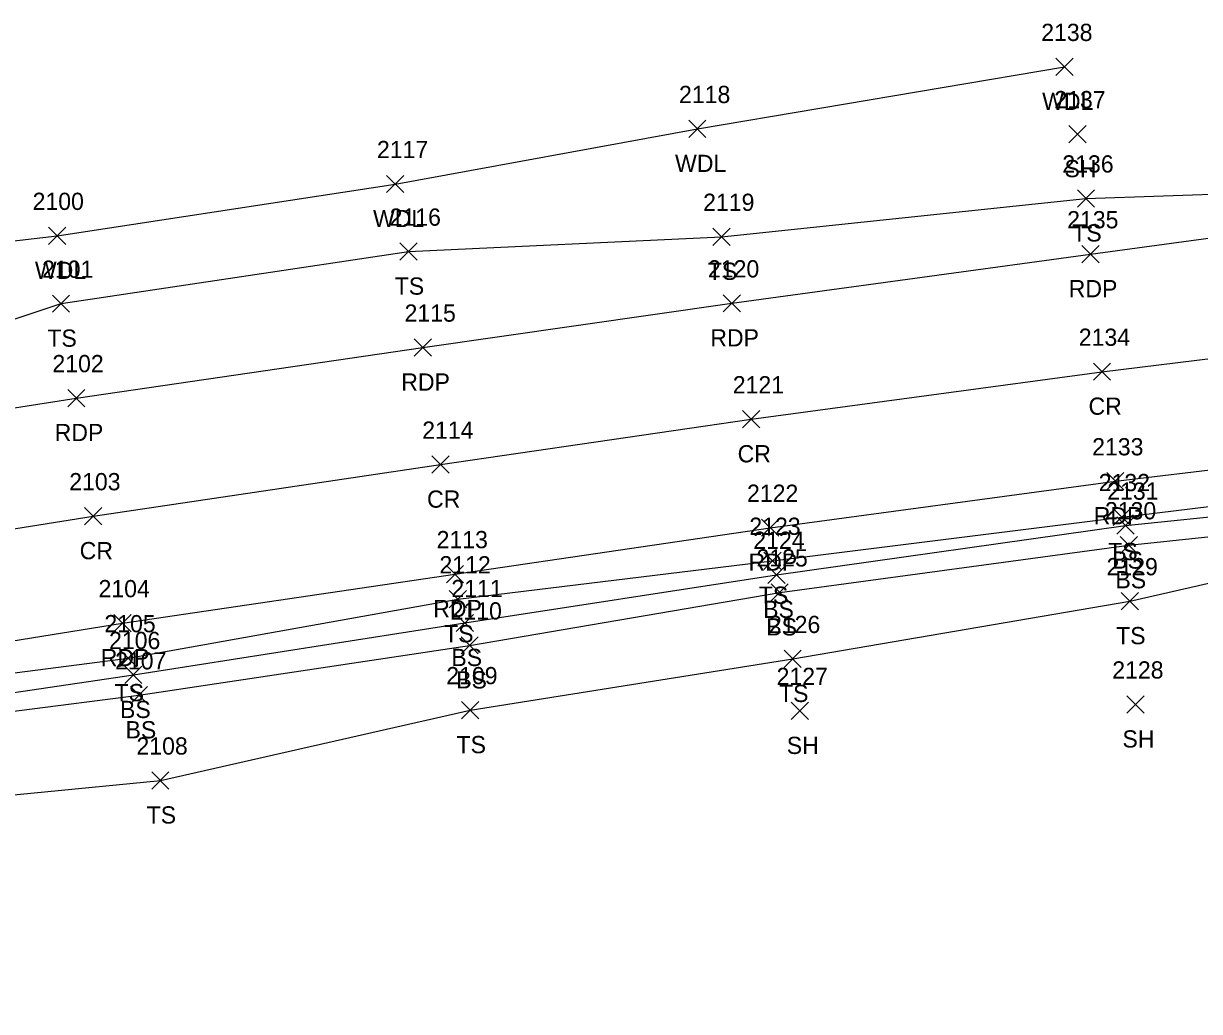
# Model space of a CAD drawing. Extents: x 1611797 to 1633212, y 298978 to 305475.
# Drawn here: x 1614515.3 to 1614651.7, y 301422 to 301536.6 of the extents above; entities that cross this region are included whole.
import ezdxf

# ---------------------------------------------------------------- set-up
doc = ezdxf.new("R2010")
doc.units = 0
for name, color, linetype in [('L_A', 7, 'Continuous'), ('L_I', 7, 'Continuous'), ('L_TIC', 7, 'Continuous'), ('LAWA', 7, 'Continuous'), ('LELB', 7, 'Continuous'), ('P_A', 7, 'Continuous'), ('P_I', 7, 'Continuous'), ('P_TIC', 7, 'Continuous'), ('PET', 7, 'Continuous'), ('PRC', 7, 'Continuous')]:
    doc.layers.add(name, color=color, linetype=linetype)

msp = doc.modelspace()

# ---------------------------------------------------------------- linework, layer by layer
at = {"layer": 'L_TIC'}
for points in [[(1614635.08, 301530.61), (1614637.08, 301532.61)], [(1614637.08, 301530.61), (1614635.08, 301532.61)], [(1614592.49, 301523.41), (1614594.49, 301525.41)], [(1614594.49, 301523.41), (1614592.49, 301525.41)], [(1614636.59, 301522.81), (1614638.59, 301524.81)], [(1614638.59, 301522.81), (1614636.59, 301524.81)], [(1614557.44, 301517.02), (1614559.44, 301519.02)], [(1614559.44, 301517.02), (1614557.44, 301519.02)], [(1614637.57, 301515.35), (1614639.57, 301517.35)], [(1614639.57, 301515.35), (1614637.57, 301517.35)], [(1614518.22, 301511.01), (1614520.22, 301513.01)], [(1614520.22, 301511.01), (1614518.22, 301513.01)], [(1614595.29, 301510.9), (1614597.29, 301512.9)], [(1614597.29, 301510.9), (1614595.29, 301512.9)], [(1614558.97, 301509.18), (1614560.97, 301511.18)], [(1614560.97, 301509.18), (1614558.97, 301511.18)], [(1614518.67, 301503.14), (1614520.67, 301505.14)], [(1614520.67, 301503.14), (1614518.67, 301505.14)], [(1614641.74, 301478.39), (1614643.74, 301480.39)], [(1614643.74, 301478.39), (1614641.74, 301480.39)], [(1614642.17, 301477.4), (1614644.17, 301479.4)], [(1614644.17, 301477.4), (1614642.17, 301479.4)], [(1614642.55, 301475.12), (1614644.55, 301477.12)], [(1614644.55, 301475.12), (1614642.55, 301477.12)], [(1614601.21, 301473.32), (1614603.21, 301475.32)], [(1614603.21, 301473.32), (1614601.21, 301475.32)], [(1614601.68, 301471.69), (1614603.68, 301473.69)], [(1614603.68, 301471.69), (1614601.68, 301473.69)], [(1614564.7, 301468.85), (1614566.7, 301470.85)], [(1614566.7, 301468.85), (1614564.7, 301470.85)], [(1614602.04, 301469.65), (1614604.04, 301471.65)], [(1614604.04, 301469.65), (1614602.04, 301471.65)], [(1614642.66, 301468.63), (1614644.66, 301470.63)], [(1614644.66, 301468.63), (1614642.66, 301470.63)], [(1614565.51, 301466.1), (1614567.51, 301468.1)], [(1614567.51, 301466.1), (1614565.51, 301468.1)], [(1614566.07, 301463.5), (1614568.07, 301465.5)], [(1614568.07, 301463.5), (1614566.07, 301465.5)], [(1614526.47, 301462.02), (1614528.47, 301464.02)], [(1614528.47, 301462.02), (1614526.47, 301464.02)], [(1614603.55, 301461.93), (1614605.55, 301463.93)], [(1614605.55, 301461.93), (1614603.55, 301463.93)], [(1614527.06, 301460.07), (1614529.06, 301462.07)], [(1614529.06, 301460.07), (1614527.06, 301462.07)], [(1614527.71, 301457.71), (1614529.71, 301459.71)], [(1614529.71, 301457.71), (1614527.71, 301459.71)], [(1614643.31, 301456.65), (1614645.31, 301458.65)], [(1614645.31, 301456.65), (1614643.31, 301458.65)], [(1614566.14, 301455.99), (1614568.14, 301457.99)], [(1614568.14, 301455.99), (1614566.14, 301457.99)], [(1614604.37, 301455.9), (1614606.37, 301457.9)], [(1614606.37, 301455.9), (1614604.37, 301457.9)], [(1614530.19, 301447.83), (1614532.19, 301449.83)], [(1614532.19, 301447.83), (1614530.19, 301449.83)]]:
    msp.add_lwpolyline(points, dxfattribs=at)
at = {"layer": 'LAWA'}
msp.add_lwpolyline([(1614366.06, 301492.98), (1614391.26, 301497.25), (1614409.98, 301497.41), (1614429.08, 301502.06), (1614460.11, 301504.85), (1614477.42, 301507.37), (1614492.86, 301508.96), (1614519.22, 301512.01), (1614558.44, 301518.02), (1614593.49, 301524.41), (1614636.08, 301531.61)], dxfattribs=at)
at = {"layer": 'LELB'}
for points in [[(1614431.54, 301482.84), (1614462.05, 301487.3), (1614494.87, 301495.91), (1614519.67, 301504.14), (1614559.97, 301510.18), (1614596.29, 301511.9), (1614638.57, 301516.35), (1614665.6, 301517.26), (1614689.07, 301522.87)], [(1614397.99, 301442.92), (1614427.41, 301447.99), (1614467.33, 301454.21), (1614500.14, 301459.48), (1614527.47, 301463.02), (1614565.7, 301469.85), (1614602.21, 301474.32), (1614642.74, 301479.39), (1614671.43, 301482.88), (1614707.96, 301487.6), (1614751.26, 301491.29), (1614776.62, 301492.25), (1614790.7, 301492.68), (1614828.78, 301494.15), (1614870.95, 301494.61), (1614916.31, 301494.84), (1614940.92, 301495.39), (1614991.32, 301496.48), (1615024.25, 301496.97), (1615079.65, 301497.8)], [(1614388.68, 301423.66), (1614397.1, 301437.78), (1614427.86, 301446.85), (1614467.6, 301452.72), (1614486.89, 301454.32), (1614500.85, 301457.06), (1614528.06, 301461.07), (1614566.51, 301467.1), (1614602.68, 301472.69), (1614643.17, 301478.4), (1614671.68, 301481.35), (1614708.28, 301486.02), (1614751.11, 301488.75), (1614768.89, 301489.17), (1614769.01, 301487.67)], [(1614397.1, 301437.78), (1614428.41, 301444.54), (1614468.12, 301450.7), (1614487.22, 301452.99), (1614500.88, 301455.16), (1614528.71, 301458.71), (1614567.07, 301464.5), (1614603.04, 301470.65), (1614643.55, 301476.12), (1614672.08, 301479.14), (1614708.59, 301484.35), (1614751.86, 301486.59), (1614769.01, 301487.67)], [(1614398.42, 301422.03), (1614407.58, 301431.9), (1614428.91, 301436.83), (1614470.35, 301441.15), (1614511.39, 301446.9), (1614531.19, 301448.83), (1614567.14, 301456.99), (1614604.55, 301462.93), (1614643.66, 301469.63), (1614672.14, 301476.12), (1614708.74, 301481.62), (1614752.08, 301482.44), (1614770.32, 301485.06)]]:
    msp.add_lwpolyline(points, dxfattribs=at)
at = {"layer": 'P_TIC'}
for points in [[(1614638.09, 301508.88), (1614640.09, 301510.88)], [(1614640.09, 301508.88), (1614638.09, 301510.88)], [(1614596.5, 301503.18), (1614598.5, 301505.18)], [(1614598.5, 301503.18), (1614596.5, 301505.18)], [(1614560.65, 301498.05), (1614562.65, 301500.05)], [(1614562.65, 301498.05), (1614560.65, 301500.05)], [(1614639.43, 301495.25), (1614641.43, 301497.25)], [(1614641.43, 301495.25), (1614639.43, 301497.25)], [(1614520.44, 301492.19), (1614522.44, 301494.19)], [(1614522.44, 301492.19), (1614520.44, 301494.19)], [(1614598.72, 301489.73), (1614600.72, 301491.73)], [(1614600.72, 301489.73), (1614598.72, 301491.73)], [(1614562.69, 301484.47), (1614564.69, 301486.47)], [(1614564.69, 301484.47), (1614562.69, 301486.47)], [(1614640.98, 301482.54), (1614642.98, 301484.54)], [(1614642.98, 301482.54), (1614640.98, 301484.54)], [(1614522.39, 301478.49), (1614524.39, 301480.49)], [(1614524.39, 301478.49), (1614522.39, 301480.49)], [(1614600.94, 301477.15), (1614602.94, 301479.15)], [(1614602.94, 301477.15), (1614600.94, 301479.15)], [(1614564.37, 301471.77), (1614566.37, 301473.77)], [(1614566.37, 301471.77), (1614564.37, 301473.77)], [(1614525.79, 301466.08), (1614527.79, 301468.08)], [(1614527.79, 301466.08), (1614525.79, 301468.08)]]:
    msp.add_lwpolyline(points, dxfattribs=at)
at = {"layer": 'PET'}
for points in [[(1614353.18, 301466.45), (1614396.11, 301473.72), (1614432.71, 301479.37), (1614462.6, 301484.02), (1614495.94, 301489.18), (1614521.44, 301493.19), (1614561.65, 301499.05), (1614597.5, 301504.18), (1614639.09, 301509.88), (1614667, 301513.69), (1614685.25, 301515.36), (1614720.54, 301519.49), (1614750.28, 301521.49), (1614788.72, 301523.73), (1614827.23, 301525.41)], [(1614357.07, 301439.35), (1614396.41, 301445), (1614427.12, 301450.7), (1614466.81, 301457.75), (1614499.64, 301462.71), (1614526.79, 301467.08), (1614565.37, 301472.77), (1614601.94, 301478.15), (1614641.98, 301483.54), (1614671.08, 301487.02), (1614708.04, 301490.97), (1614751.42, 301494.58), (1614776.03, 301496.28), (1614791.19, 301496.95), (1614828.91, 301498.47)]]:
    msp.add_lwpolyline(points, dxfattribs=at)
at = {"layer": 'PRC'}
msp.add_lwpolyline([(1614363.42, 301453.92), (1614394.65, 301458.77), (1614425.51, 301463.7), (1614464.79, 301470.26), (1614497.93, 301475.41), (1614523.39, 301479.49), (1614563.69, 301485.47), (1614599.72, 301490.73), (1614640.43, 301496.25), (1614669.39, 301499.77), (1614706.96, 301503.6), (1614752.46, 301507.37), (1614790.97, 301509.52), (1614828.29, 301511.16), (1614871, 301512.22), (1614916.11, 301513.02), (1614945.75, 301513.16), (1615002.39, 301512.78), (1615048.11, 301512.72), (1615086.61, 301512.12), (1615113.26, 301511.44), (1615142.89, 301510.74), (1615196.64, 301509.68)], dxfattribs=at)

# ---------------------------------------------------------------- texts
at = {"layer": 'L_A'}
for s, p in [('WDL', (1614633.49, 301526.61)), ('WDL', (1614590.9, 301519.41)), ('SH', (1614636.08, 301518.81)), ('WDL', (1614555.86, 301513.02)), ('TS', (1614636.98, 301511.35)), ('WDL', (1614516.64, 301507.01)), ('TS', (1614594.7, 301506.9)), ('TS', (1614558.38, 301505.18)), ('TS', (1614518.08, 301499.14)), ('TS', (1614641.15, 301474.39)), ('BS', (1614641.61, 301473.4)), ('BS', (1614641.99, 301471.12)), ('TS', (1614600.62, 301469.32)), ('BS', (1614601.12, 301467.69)), ('BS', (1614601.48, 301465.65)), ('TS', (1614564.11, 301464.85)), ('TS', (1614642.07, 301464.63)), ('BS', (1614564.95, 301462.1)), ('BS', (1614565.51, 301459.5)), ('TS', (1614525.88, 301458.02)), ('TS', (1614602.96, 301457.93)), ('BS', (1614526.51, 301456.07)), ('BS', (1614527.15, 301453.71)), ('TS', (1614565.55, 301451.99)), ('SH', (1614642.8, 301452.65)), ('SH', (1614603.86, 301451.9)), ('TS', (1614529.6, 301443.83))]:
    msp.add_text(s, height=2, dxfattribs=at).set_placement(p)
at = {"layer": 'L_I'}
for s, p in [('2138', (1614633.38, 301534.61)), ('2118', (1614591.36, 301527.41)), ('2137', (1614634.9, 301526.81)), ('2117', (1614556.32, 301521.02)), ('2136', (1614635.83, 301519.35)), ('2100', (1614516.37, 301515.01)), ('2119', (1614594.16, 301514.9)), ('2116', (1614557.79, 301513.18)), ('2101', (1614517.47, 301507.14)), ('2132', (1614640.05, 301482.39)), ('2131', (1614641.04, 301481.4)), ('2130', (1614640.77, 301479.12)), ('2123', (1614599.52, 301477.32)), ('2124', (1614599.98, 301475.69)), ('2112', (1614563.57, 301472.85)), ('2125', (1614600.35, 301473.65)), ('2129', (1614640.96, 301472.63)), ('2111', (1614564.95, 301470.1)), ('2110', (1614564.86, 301467.5)), ('2105', (1614524.7, 301466.02)), ('2126', (1614601.8, 301465.93)), ('2106', (1614525.24, 301464.07)), ('2107', (1614525.94, 301461.71)), ('2128', (1614641.62, 301460.65)), ('2109', (1614564.36, 301459.99)), ('2127', (1614602.68, 301459.9)), ('2108', (1614528.42, 301451.83))]:
    msp.add_text(s, height=2, dxfattribs=at).set_placement(p)
at = {"layer": 'P_A'}
for s, p in [('RDP', (1614636.57, 301504.88)), ('RDP', (1614594.99, 301499.18)), ('RDP', (1614559.14, 301494.05)), ('CR', (1614638.87, 301491.25)), ('RDP', (1614518.93, 301488.19)), ('CR', (1614598.16, 301485.73)), ('CR', (1614562.13, 301480.47)), ('RDP', (1614639.47, 301478.54)), ('CR', (1614521.83, 301474.49)), ('RDP', (1614599.43, 301473.15)), ('RDP', (1614562.85, 301467.77)), ('RDP', (1614524.28, 301462.08))]:
    msp.add_text(s, height=2, dxfattribs=at).set_placement(p)
at = {"layer": 'P_I'}
for s, p in [('2135', (1614636.39, 301512.88)), ('2120', (1614594.72, 301507.18)), ('2115', (1614559.52, 301502.05)), ('2134', (1614637.74, 301499.25)), ('2102', (1614518.67, 301496.19)), ('2121', (1614597.6, 301493.73)), ('2114', (1614561.57, 301488.47)), ('2133', (1614639.29, 301486.54)), ('2103', (1614520.62, 301482.49)), ('2122', (1614599.25, 301481.15)), ('2113', (1614563.24, 301475.77)), ('2104', (1614524.02, 301470.08))]:
    msp.add_text(s, height=2, dxfattribs=at).set_placement(p)

doc.saveas('drawing.dxf')
